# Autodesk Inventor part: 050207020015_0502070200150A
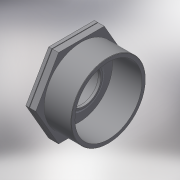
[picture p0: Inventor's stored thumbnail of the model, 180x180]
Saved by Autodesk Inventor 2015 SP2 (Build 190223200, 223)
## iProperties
Created: 2017-05
Part Number: 050207020015_0502070200150A
Material: Generic
Description: PLASSON REDUCING BUSHING 2"-1.1/2"
Document SubType Name: Modeling
Designer: KIM
Density: 1 g/cm^3
Appearance: Default
Author: KIM
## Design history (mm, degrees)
derived "050207.ipt"
feature "Solid1::050207.ipt"
tag "TaggingFeature1"
body "Solid1"
other parameters: "d1" = 59.614, "d2" = 63, "d5" = 26, "d8" = 0.41, "d12" = 0, "d15" = 41, "d19" = 0, "d30" = 9.11111, "d31" = 4.55556, "d33" = 44.845, "d34" = 53.6526, "d36" = 3.15, "d37" = 49.3295, "d38" = 27.06, "d39" = 40.3605, "d40" = 2.6, "d41" = 0, "H_" = 41, "R_" = 59.614, "E_" = 63, "l_2" = 26, "Rp_" = 44.845
